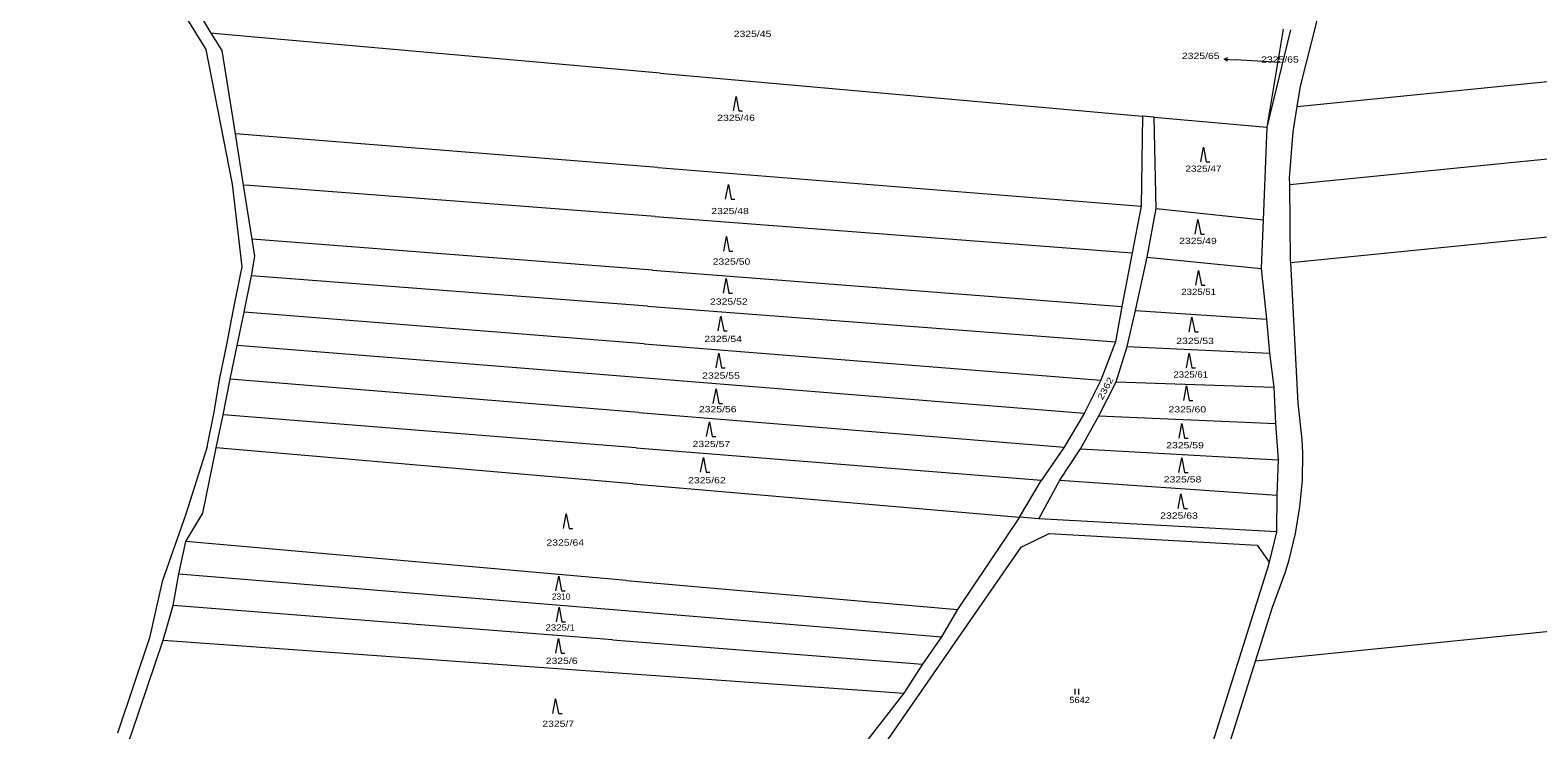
# Model space of a CAD drawing. Extents: x -590528 to -586543, y -1119609 to -1116685.
# Drawn here: x -588462.9 to -588051.1, y -1117388.3 to -1117197.2 of the extents above; entities that cross this region are included whole.
import ezdxf
from ezdxf.enums import TextEntityAlignment as Align

# ---------------------------------------------------------------- set-up
doc = ezdxf.new("R2010")
doc.units = 0
doc.header["$LTSCALE"] = 0.68
for name, color, linetype, lineweight in [('1', 7, 'Continuous', 13), ('3', 7, 'Continuous', 13), ('6', 7, 'Continuous', 13)]:
    doc.layers.add(name, color=color, linetype=linetype, lineweight=lineweight)

msp = doc.modelspace()

# ---------------------------------------------------------------- linework, layer by layer
at = {"layer": '1'}
for p, q in [((-588410.41, -1117202.68), (-588413.4, -1117198.02)), ((-588120.58, -1117196.93), (-588125.07, -1117223.64)), ((-588118.59, -1117197.09), (-588125.07, -1117223.64)), ((-588407.57, -1117239.25), (-588414.79, -1117202.47)), ((-588116.81, -1117218), (-587938.48, -1117200.2)), ((-588290.82, -1117208.92), (-588159.05, -1117220.64)), ((-588159.05, -1117220.64), (-588159.39, -1117245.27)), ((-588155.88, -1117220.9), (-588159.05, -1117220.64)), ((-588155.88, -1117220.9), (-588125.07, -1117223.64)), ((-588118.84, -1117239.34), (-587942.86, -1117221.77)), ((-588291.4, -1117234.7), (-588406.79, -1117225.46)), ((-588291.4, -1117234.7), (-588159.39, -1117245.27)), ((-588402.84, -1117239.61), (-588404.56, -1117239.48)), ((-588292.11, -1117248.07), (-588402.84, -1117239.61)), ((-588118.84, -1117239.34), (-588118.86, -1117237.48)), ((-588292.11, -1117248.07), (-588161.87, -1117258.01)), ((-588159.39, -1117245.27), (-588161.87, -1117258.01)), ((-588155.27, -1117245.83), (-588126.11, -1117248.97)), ((-588292.89, -1117262.71), (-588402.22, -1117254.22)), ((-588157.73, -1117259.18), (-588126.6, -1117262.22)), ((-588294.21, -1117272.52), (-588402.4, -1117264.23)), ((-588292.89, -1117262.71), (-588164.69, -1117272.66)), ((-588294.21, -1117272.52), (-588166.41, -1117282.32)), ((-588160.92, -1117273.69), (-588125.17, -1117276.1)), ((-588295.12, -1117282.83), (-588404.43, -1117274.15)), ((-588295.87, -1117292.12), (-588406.3, -1117283.26)), ((-588295.12, -1117282.83), (-588170.46, -1117292.74)), ((-588163.23, -1117283.52), (-588124.39, -1117285.38)), ((-588296.64, -1117301.59), (-588408.19, -1117292.48)), ((-588174.98, -1117301.83), (-588295.87, -1117292.12)), ((-588166.22, -1117293.25), (-588123.19, -1117294.66)), ((-588297.35, -1117311.23), (-588410.18, -1117302.19)), ((-588296.64, -1117301.59), (-588180.44, -1117311.09)), ((-588170.95, -1117302.51), (-588122.73, -1117304.58)), ((-588298.21, -1117321.07), (-588412.03, -1117311.2)), ((-588297.35, -1117311.23), (-588186.63, -1117320.1)), ((-588175.98, -1117311.49), (-588122.03, -1117314.52)), ((-588298.21, -1117321.07), (-588192.63, -1117330.22)), ((-588192.63, -1117330.22), (-588186.63, -1117320.1)), ((-588187.38, -1117330.59), (-588181.64, -1117320.09)), ((-588181.64, -1117320.09), (-588122.31, -1117324.13)), ((-588122.31, -1117324.13), (-588122.41, -1117334.15)), ((-588300.01, -1117347.45), (-588420.38, -1117336.84)), ((-588127.77, -1117337.83), (-588124.43, -1117342.46)), ((-588422.28, -1117345.62), (-588302.5, -1117355.52)), ((-588300.01, -1117347.45), (-588209.61, -1117355.42)), ((-588303.81, -1117363.69), (-588423.79, -1117354.28)), ((-588302.5, -1117355.52), (-588213.97, -1117362.84)), ((-588426.5, -1117363.77), (-588306.04, -1117372.41)), ((-588303.81, -1117363.69), (-588219.12, -1117370.33)), ((-588306.04, -1117372.41), (-588224.19, -1117378.28)), ((-588153.73, -1117450.69), (-588128.15, -1117369.47))]:
    msp.add_line(p, q, dxfattribs=at)
for points in [[(-588414.79, -1117202.47), (-588449.21, -1117146.57), (-588462.86, -1117114.04)], [(-588413.4, -1117198.02), (-588428.26, -1117172.92), (-588436.11, -1117159.66), (-588443.66, -1117147.09)], [(-588116.81, -1117218), (-588115.91, -1117212.47), (-588112.84, -1117200.24), (-588110.37, -1117190.52), (-588105.66, -1117174.66)], [(-588290.82, -1117208.92), (-588411.77, -1117198.17), (-588413.4, -1117198.02)], [(-588404.56, -1117239.48), (-588406.79, -1117225.46), (-588410.41, -1117202.68)], [(-588118.86, -1117237.48), (-588117.92, -1117224.91), (-588116.81, -1117218)], [(-588157.73, -1117259.18), (-588155.27, -1117245.83), (-588155.88, -1117220.9)], [(-588125.07, -1117223.64), (-588126.11, -1117248.97), (-588126.6, -1117262.22), (-588125.17, -1117276.1), (-588124.39, -1117285.38), (-588123.19, -1117294.66), (-588122.73, -1117304.58), (-588122.03, -1117314.52), (-588122.31, -1117324.13)], [(-588414.52, -1117310.98), (-588412.67, -1117301.99), (-588411.01, -1117292.25), (-588409.11, -1117283.03), (-588407.39, -1117273.91), (-588405.41, -1117264), (-588404.97, -1117261.8), (-588405.88, -1117253.94), (-588407.57, -1117239.25)], [(-588402.4, -1117264.23), (-588401.47, -1117258.93), (-588402.22, -1117254.22), (-588404.56, -1117239.48)], [(-588118.56, -1117260.65), (-588118.58, -1117260.11), (-588118.72, -1117250.1), (-588118.84, -1117239.34)], [(-588116.05, -1117327.38), (-588115.39, -1117320.04), (-588115.26, -1117312.67), (-588115.46, -1117308.98), (-588116.49, -1117299.02), (-588118.56, -1117260.65), (-587960.09, -1117244.82)], [(-588161.87, -1117258.01), (-588164.69, -1117272.66), (-588166.41, -1117282.32), (-588170.46, -1117292.74)], [(-588166.22, -1117293.25), (-588163.23, -1117283.52), (-588160.92, -1117273.69), (-588157.73, -1117259.18)], [(-588420.38, -1117336.84), (-588415.71, -1117329.12), (-588412.03, -1117311.2), (-588410.18, -1117302.19), (-588408.19, -1117292.48), (-588406.3, -1117283.26), (-588404.43, -1117274.15), (-588402.4, -1117264.23)], [(-588170.46, -1117292.74), (-588174.98, -1117301.83), (-588180.44, -1117311.09), (-588186.63, -1117320.1)], [(-588181.64, -1117320.09), (-588175.98, -1117311.49), (-588170.95, -1117302.51), (-588166.22, -1117293.25)], [(-588414.52, -1117310.98), (-588420.32, -1117329.35), (-588426.82, -1117347.72), (-588430.23, -1117363.16), (-588439.01, -1117389.17)], [(-587975.52, -1117354.13), (-588128.15, -1117369.47), (-588123.53, -1117354.74), (-588120.05, -1117345.36), (-588118.95, -1117341.84), (-588117.24, -1117334.66), (-588116.05, -1117327.38)], [(-588192.63, -1117330.22), (-588209.61, -1117355.42), (-588213.97, -1117362.84), (-588219.12, -1117370.33), (-588224.19, -1117378.28), (-588244.16, -1117403.92), (-588253, -1117415.47)], [(-588122.41, -1117334.15), (-588187.38, -1117330.59), (-588192.63, -1117330.22)], [(-588242.5, -1117417.41), (-588240.53, -1117411.42), (-588237.88, -1117405.69), (-588234.59, -1117400.29), (-588229.2, -1117391.88), (-588192.21, -1117338.37), (-588184.52, -1117334.61), (-588127.77, -1117337.83)], [(-588122.41, -1117334.15), (-588124.43, -1117342.46), (-588124.82, -1117343.85), (-588154.4, -1117437.8)], [(-588444.36, -1117414.31), (-588439.44, -1117400.97), (-588435.13, -1117389.07), (-588426.5, -1117363.77), (-588423.79, -1117354.28), (-588422.28, -1117345.62), (-588420.38, -1117336.84)]]:
    msp.add_lwpolyline(points, dxfattribs=at)
at = {"layer": '3'}
for p in [(-588136.774, -1117205.042), (-588121.5, -1117206.02)]:
    msp.add_line(p, (-588133.78, -1117205.23), dxfattribs=at)
msp.add_lwpolyline([(-588135.808, -1117205.602), (-588136.774, -1117205.042), (-588135.744, -1117204.605)], dxfattribs=at)
at = {"layer": '6'}
for p, q in [((-588177.46, -1117378.59), (-588177.46, -1117377.09)), ((-588176.46, -1117378.59), (-588176.46, -1117377.09))]:
    msp.add_line(p, q, dxfattribs=at)
for points in [[(-588270.8, -1117219.24), (-588270.05, -1117215.24), (-588269.3, -1117219.24), (-588268.3, -1117219.24)], [(-588143.15, -1117233.14), (-588142.4, -1117229.14), (-588141.65, -1117233.14), (-588140.65, -1117233.14)], [(-588272.91, -1117243.33), (-588272.16, -1117239.33), (-588271.41, -1117243.33), (-588270.41, -1117243.33)], [(-588144.65, -1117252.87), (-588143.9, -1117248.87), (-588143.15, -1117252.87), (-588142.15, -1117252.87)], [(-588273.42, -1117257.49), (-588272.67, -1117253.49), (-588271.92, -1117257.49), (-588270.92, -1117257.49)], [(-588273.51, -1117268.97), (-588272.76, -1117264.97), (-588272.01, -1117268.97), (-588271.01, -1117268.97)], [(-588144.46, -1117266.77), (-588143.71, -1117262.77), (-588142.96, -1117266.77), (-588141.96, -1117266.77)], [(-588274.94, -1117279.26), (-588274.19, -1117275.26), (-588273.44, -1117279.26), (-588272.44, -1117279.26)], [(-588146.29, -1117279.57), (-588145.54, -1117275.57), (-588144.79, -1117279.57), (-588143.79, -1117279.57)], [(-588275.53, -1117289.41), (-588274.78, -1117285.41), (-588274.03, -1117289.41), (-588273.03, -1117289.41)], [(-588147.06, -1117289.36), (-588146.31, -1117285.36), (-588145.56, -1117289.36), (-588144.56, -1117289.36)], [(-588147.78, -1117298.27), (-588147.03, -1117294.27), (-588146.28, -1117298.27), (-588145.28, -1117298.27)], [(-588276.27, -1117299.11), (-588275.52, -1117295.11), (-588274.77, -1117299.11), (-588273.77, -1117299.11)], [(-588278.09, -1117308.1), (-588277.34, -1117304.1), (-588276.59, -1117308.1), (-588275.59, -1117308.1)], [(-588149.03, -1117308.64), (-588148.28, -1117304.64), (-588147.53, -1117308.64), (-588146.53, -1117308.64)], [(-588279.73, -1117317.86), (-588278.98, -1117313.86), (-588278.23, -1117317.86), (-588277.23, -1117317.86)], [(-588149.08, -1117317.95), (-588148.33, -1117313.95), (-588147.58, -1117317.95), (-588146.58, -1117317.95)], [(-588149.29, -1117327.77), (-588148.54, -1117323.77), (-588147.79, -1117327.77), (-588146.79, -1117327.77)], [(-588317.18, -1117333.3), (-588316.43, -1117329.3), (-588315.68, -1117333.3), (-588314.68, -1117333.3)], [(-588319.24, -1117350.3), (-588318.49, -1117346.3), (-588317.74, -1117350.3), (-588316.74, -1117350.3)], [(-588319.12, -1117358.75), (-588318.37, -1117354.75), (-588317.62, -1117358.75), (-588316.62, -1117358.75)], [(-588319.3, -1117367.36), (-588318.55, -1117363.36), (-588317.8, -1117367.36), (-588316.8, -1117367.36)], [(-588320.08, -1117383.76), (-588319.33, -1117379.76), (-588318.58, -1117383.76), (-588317.58, -1117383.76)]]:
    msp.add_lwpolyline(points, dxfattribs=at)

# ---------------------------------------------------------------- texts
at = {"layer": '3'}
for s, width, p in [('2325/45', 1.25, (-588265.5505, -1117199.02)), ('2325/65', 1.25, (-588121.5005, -1117206.02)), ('2325/46', 1.25, (-588270.0505, -1117221.94)), ('2325/47', 1.2, (-588142.4005, -1117235.84)), ('2325/48', 1.25, (-588271.7, -1117247.41)), ('2325/49', 1.25, (-588143.9005, -1117255.57)), ('2325/50', 1.25, (-588271.3105, -1117261.22)), ('2325/51', 1.15, (-588143.7105, -1117269.47)), ('2325/52', 1.25, (-588272.021, -1117272.14)), ('2325/54', 1.25, (-588273.5905, -1117282.35)), ('2325/53', 1.25, (-588144.6805, -1117282.89)), ('2325/61', 1.15, (-588145.8805, -1117292.05)), ('2325/55', 1.25, (-588274.1705, -1117292.36)), ('2325/56', 1.25, (-588275.0605, -1117301.55)), ('2325/60', 1.25, (-588146.8105, -1117301.58)), ('2325/57', 1.25, (-588276.8005, -1117311.04)), ('2325/59', 1.25, (-588147.4205, -1117311.39)), ('2325/62', 1.25, (-588278.0205, -1117320.94)), ('2325/58', 1.25, (-588148.11, -1117320.7)), ('2325/63', 1.25, (-588149.0705, -1117330.59)), ('2325/64', 1.25, (-588316.7105, -1117337.96)), ('2325/1', 1.15, (-588318.0905, -1117361.15)), ('2325/6', 1.25, (-588317.6905, -1117370.26)), ('2325/7', 1.25, (-588318.631, -1117387.44))]:
    msp.add_text(s, height=1.7, dxfattribs=dict(at, width=width)).set_placement(p, align=Align.CENTER)
at = {"layer": '3', "width": 1.25}
msp.add_text('2325/65', height=1.7, dxfattribs=at).set_placement((-588138.009, -1117205.04), align=Align.RIGHT)
at = {"layer": '3', "width": 1.3}
msp.add_text('2362', height=1.7, rotation=61.765, dxfattribs=at).set_placement((-588169.978, -1117298.301))
at = {"layer": '3'}
msp.add_text('2310', height=1.7, dxfattribs=at).set_placement((-588320.343, -1117352.71))
at = {"layer": '3', "width": 1.1}
msp.add_text('5642', height=1.7, dxfattribs=at).set_placement((-588179.003, -1117380.95))

doc.saveas('drawing.dxf')
